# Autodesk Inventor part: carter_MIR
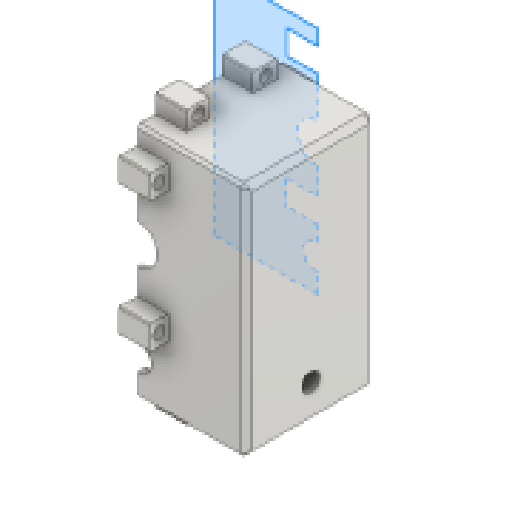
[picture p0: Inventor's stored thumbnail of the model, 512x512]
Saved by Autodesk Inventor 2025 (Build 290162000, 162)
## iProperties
Created: 2026-05
Part Number: carter_MIR
Material: Acciaio
Document SubType Name: Modeling
Designer: Ryzen5700u
Density: 7.85 g/cm^3
Appearance: Acciaio
Author: R5800u
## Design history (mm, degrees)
derived "carter.ipt"
  sketch "Schizzo1"
    geometry: L1 (0, -58)-(-160, -58) reference; L2 (-160, -58)-(-160, 332) reference; L3 (-160, 332)-(0, 332) reference; L4 (0, 332)-(0, -58) reference; C1 r 12 at (0, 0) reference; C2 r 31 at (0, 0) reference; C3 r 45 at (0, 162) reference; A1 r 19.5 centre (0, 162) between (18.547, 168.023) and (18.561, 156.023) reference; 1 further point
  sketch "Schizzo2"
    geometry: L1 (0, 390)-(-35, 390) reference; L2 (-210, 0)-(-210, 390) reference; L3 (0, 390)-(-210, 390) reference; L4 (-210, 390)-(-210, 0) reference; L5 (-210, 0)-(0, 0) reference; L6 (0, 0)-(0, 390) reference; 1 further point
  sketch "Schizzo3"
    geometry: L1 (175, 390)-(35, 390) reference; L2 (175, 390)-(175, 0) reference; L3 (35, 390)-(175, 390) reference; L4 (175, 390)-(175, 370) reference; L5 (175, 370)-(35, 370) reference; L6 (35, 370)-(35, 390) reference; L7 (0, 0)-(35, 0) reference; L8 (35, 0)-(175, 0) reference; L9 (175, 0)-(175, 20) reference; L10 (175, 20)-(35, 20) reference; L11 (35, 20)-(35, 0) reference; 1 further point
  sketch "Schizzo4"
    geometry: L1 (0, 170)-(0, 45) reference; L2 (0, 170)-(180, 170) reference; L3 (180, -220)-(180, 170) reference; L4 (0, -220)-(180, -220) reference; L5 (0, -193)-(0, -220) reference; L6 (0, -45)-(0, -131) reference; L7 (0, 45)-(0, -45) reference; C1 r 32.5 at (0, 0) reference; A1 r 31 centre (0, -162) between (0, -193) and (0, -131) reference; A2 r 45 centre (0, 0) between (0, -45) and (0, 45) reference; 1 further point
  sketch "Schizzo5"
    geometry: L1 (0, 332)-(0, 194.5) reference; L2 (0, 332)-(180, 332) reference; L3 (180, -58)-(180, 332) reference; L4 (0, -58)-(180, -58) reference; L5 (0, -31)-(0, -58) reference; L6 (0, 31)-(0, 129.5) reference; L7 (0, 31)-(0, -31) reference; C1 r 21 at (1.789, 0) reference; A1 r 31 centre (0, 0) between (0, -31) and (0, 31) reference; A2 r 32.5 centre (0, 162) between (0, 129.5) and (0, 194.5) reference; 1 further point
  sketch "Schizzo6"
    geometry: L1 (35, 120)-(30, 125) reference; L2 (35, 120)-(35, -12.5) reference; L3 (35, -12.5)-(28, -12.5) reference; L4 (28, 0)-(28, -12.5) reference; L5 (28, 0)-(0, 0) reference; L6 (0, 0)-(0, 105) reference; L7 (-140, 105)-(0, 105) reference; L8 (-140, 0)-(-140, 105) reference; L9 (-168, 0)-(-140, 0) reference; L10 (-168, 0)-(-168, -12.5) reference; L11 (-175, -12.5)-(-168, -12.5) reference; L12 (-175, 120)-(-175, -12.5) reference; L13 (-170, 125)-(-175, 120) reference; L14 (-170, 125)-(30, 125) reference; L15 (-175, -260)-(-170, -265) reference; L16 (-175, -227.924)-(-175, -260) reference; L17 (-175, -227.924)-(-162, -227.924) reference; L18 (-162, -227.924)-(-162, -238) reference; L19 (-162, -238)-(-140, -238) reference; L20 (-140, -245)-(-140, -238) reference; L21 (0, -245)-(-140, -245) reference; L22 (0, -245)-(0, -238) reference; L23 (22, -238)-(0, -238) reference; L24 (22, -227.924)-(22, -238) reference; L25 (35, -227.924)-(22, -227.924) reference; L26 (35, -260)-(35, -227.924) reference; L27 (30, -265)-(35, -260) reference; L28 (-170, -265)-(30, -265) reference; L29 (-175, -77.5)-(-175, -186.076) reference; L30 (-175, -77.5)-(-168, -77.5) reference; L31 (-168, -77.5)-(-168, -90) reference; L32 (-168, -90)-(-140, -90) reference; L33 (-140, -176)-(-140, -90) reference; L34 (-162, -176)-(-140, -176) reference; L35 (-162, -176)-(-162, -186.076) reference; L36 (-175, -186.076)-(-162, -186.076) reference; L37 (35, -186.076)-(35, -77.5) reference; L38 (35, -186.076)-(22, -186.076) reference; L39 (22, -176)-(22, -186.076) reference; L40 (22, -176)-(0, -176) reference; L41 (0, -176)-(0, -90) reference; L42 (28, -90)-(0, -90) reference; L43 (28, -77.5)-(28, -90) reference; L44 (35, -77.5)-(28, -77.5) reference; L45 (-125, 125)-(-125, -265) reference; L46 (30, 125)-(-170, 125) reference; L47 (-70, 125)-(-70, -265) reference; L48 (-15, 125)-(-15, -265) reference; L49 (-175, 75)-(35, 75) reference; L50 (35, -260)-(35, 120) reference; L51 (-145, 95)-(-205, 95) reference; L52 (-205, 95)-(-205, 55) reference; L53 (-205, 55)-(-145, 55) reference; L54 (-145, 55)-(-145, 95) reference; L55 (-145, 95)-(-205, 55) reference; L56 (-205, 95)-(-145, 55) reference; L57 (-145, -235)-(-105, -235) reference; L58 (-105, -235)-(-105, -295) reference; L59 (-105, -295)-(-145, -295) reference; L60 (-145, -295)-(-145, -235) reference; L61 (-145, -235)-(-105, -295) reference; L62 (-105, -235)-(-145, -295) reference; L63 (-35, -235)-(5, -235) reference; L64 (5, -235)-(5, -295) reference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
  sketch "Schizzo7"
    geometry: L1 (35, 120)-(30, 125) reference; L2 (35, 120)-(35, 95) reference; L3 (35, 95)-(65, 95) reference; L4 (65, 95)-(65, 55) reference; L5 (65, 55)-(35, 55) reference; L6 (35, 55)-(35, -12.5) reference; L7 (35, -12.5)-(28, -12.5) reference; L8 (28, 0)-(28, -12.5) reference; L9 (28, 0)-(0, 0) reference; L10 (0, 0)-(0, 105) reference; L11 (-140, 105)-(0, 105) reference; L12 (-140, 0)-(-140, 105) reference; L13 (-168, 0)-(-140, 0) reference; L14 (-168, 0)-(-168, -12.5) reference; L15 (-175, -12.5)-(-168, -12.5) reference; L16 (-175, 55)-(-175, -12.5) reference; L17 (-175, 55)-(-205, 55) reference; L18 (-205, 55)-(-205, 95) reference; L19 (-205, 95)-(-175, 95) reference; L20 (-175, 120)-(-175, 95) reference; L21 (-170, 125)-(-175, 120) reference; L22 (-170, 125)-(-145, 125) reference; L23 (-145, 125)-(-145, 155) reference; L24 (-145, 155)-(-105, 155) reference; L25 (-105, 155)-(-105, 125) reference; L26 (-105, 125)-(-35, 125) reference; L27 (-35, 125)-(-35, 155) reference; L28 (-35, 155)-(5, 155) reference; L29 (5, 155)-(5, 125) reference; L30 (5, 125)-(30, 125) reference; L31 (35, -186.076)-(35, -160) reference; L32 (35, -186.076)-(22, -186.076) reference; L33 (22, -176)-(22, -186.076) reference; L34 (22, -176)-(0, -176) reference; L35 (0, -176)-(0, -90) reference; L36 (28, -90)-(0, -90) reference; L37 (28, -77.5)-(28, -90) reference; L38 (35, -77.5)-(28, -77.5) reference; L39 (35, -120)-(35, -77.5) reference; L40 (35, -120)-(65, -120) reference; L41 (65, -120)-(65, -160) reference; L42 (65, -160)-(35, -160) reference; L43 (5, -265)-(-35, -265) reference; L44 (-175, -260)-(-170, -265) reference; L45 (-175, -227.924)-(-175, -260) reference; L46 (-175, -227.924)-(-162, -227.924) reference; L47 (-162, -227.924)-(-162, -238) reference; L48 (-162, -238)-(-140, -238) reference; L49 (-140, -245)-(-140, -238) reference; L50 (0, -245)-(-140, -245) reference; L51 (0, -245)-(0, -238) reference; L52 (22, -238)-(0, -238) reference; L53 (22, -227.924)-(22, -238) reference; L54 (35, -227.924)-(22, -227.924) reference; L55 (35, -260)-(35, -227.924) reference; L56 (30, -265)-(35, -260) reference; L57 (5, -265)-(30, -265) reference; L58 (5, -265)-(5, -295) reference; L59 (5, -295)-(-35, -295) reference; L60 (-35, -295)-(-35, -265) reference; L61 (-105, -265)-(-35, -265) reference; L62 (-105, -265)-(-105, -295) reference; L63 (-105, -295)-(-145, -295) reference; L64 (-145, -295)-(-145, -265) reference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; 9 further points
  sketch "Schizzo8"
    geometry: L1 (-160, 30)-(-160, 170) reference; L2 (-160, 100)-(-144, 100) reference; 1 further point
  node "Piano di lavoro1"
  node "Piano di lavoro2"
  node "Piano di lavoro3"
  node "Piano di lavoro4"
sketch "Schizzo9"
  geometry: L1 (80, 65)-(0, 65) reference; L2 (80, 65)-(80, 25) reference; L3 (0, 25)-(80, 25) reference; L4 (0, 0)-(0, 25) reference; L5 (0, 0)-(145, 0) reference; L6 (180, 50)-(180, 150) reference; L7 (145, 200)-(0, 200) reference; L8 (0, 175)-(0, 200) reference; L9 (80, 175)-(0, 175) reference; L10 (80, 175)-(80, 135) reference; L11 (0, 135)-(80, 135) reference; L12 (0, 65)-(0, 135) reference; L13 (180, 50)-(145, 50) reference; L14 (145, 150)-(180, 150) reference; L15 (145, 0)-(145, 50) reference; L16 (145, 150)-(145, 200) reference; C1 r 14.917 at (144, 100) reference; 1 further point
extrude "Estrusione1" join sketch "Schizzo9" stored distance "d1" = 10; taper "d2" = 0 deg
sketch "Schizzo10"
  geometry: L1 (5, 385)-(0, 380) reference; L2 (0, 0)-(0, 380) reference; L3 (0, 0)-(5, -5) reference; L4 (155, -5)-(55, -5) reference; L5 (205, -5)-(210, 0) reference; L6 (210, 380)-(210, 0) reference; L7 (210, 380)-(205, 385) reference; L8 (55, 385)-(155, 385) reference; L9 (5, -50)-(5, -5) reference; L10 (50, -55)-(10, -55) reference; L11 (55, -5)-(55, -50) reference; L12 (155, -50)-(155, -5) reference; L13 (200, -55)-(160, -55) reference; L14 (205, -5)-(205, -50) reference; L15 (205, 430)-(205, 385) reference; L16 (160, 435)-(200, 435) reference; L17 (155, 385)-(155, 430) reference; L18 (55, 430)-(55, 385) reference; L19 (10, 435)-(50, 435) reference; L20 (5, 385)-(5, 430) reference; L21 (205, 430)-(200, 435) reference; L22 (160, 435)-(155, 430) reference; L23 (55, 430)-(50, 435) reference; L24 (10, 435)-(5, 430) reference; L25 (5, -50)-(10, -55) reference; L26 (50, -55)-(55, -50) reference; L27 (155, -50)-(160, -55) reference; L28 (200, -55)-(205, -50) reference; L29 (5, -5)-(205, -5); L30 (5, 385)-(205, 385); C1 r 270.277 at (103.909, 191.96); 6 further points
  constraints: 4 end point, 1 centre point, 1 horizontal, 1 parallel, 1 point on line
extrude "Estrusione2" cut sketch "Schizzo10" distance "d3" = 130; taper "d4" = 0 deg
sketch "Schizzo11"
  geometry: C1 r 5.053 at (225, 335) reference; C2 r 5.053 at (225, 120) reference; C3 r 5.053 at (160, 400) reference; C4 r 5.053 at (50, 400) reference; C5 r 5.053 at (-15, 335) reference; C6 r 5.053 at (-15, 120) reference; C7 r 5.053 at (50, -20) reference; C8 r 5.053 at (160, -20) reference; 1 further point
hole "Foro1" sketch "Schizzo11" at (-15, 335), (-15, 120), (50, -20), (160, -20), (225, 120), (225, 335), (160, 400), (50, 400) diameter "d5" = 10.106; stored, may be unused: countersink angle "d9" = 90 deg, drill point angle "d11" = 118 deg; dims "d6" = 24, "d7" = 20, "d8" = 15, "d10" = 8
chamfer "Smusso1" distance "d12" = 10; stored, may be unused: second distance "d13" = 2, angle "d14" = 45 deg
sketch "Schizzo12"
  geometry: L1 (-60, -10)-(-130, -10) reference; L2 (-95, -10)-(-95, 50); 1 further point
  constraints: 2 end point, 1 midpoint, 1 vertical
  dimensions: "d15" = 60 distance of L2.start L2.end
hole "Foro2" sketch "Schizzo12" at (-95, 50) diameter "d16" = 29.83494; stored, may be unused: countersink angle "d20" = 90 deg, drill point angle "d22" = 118 deg; dims "d17" = 64, "d18" = 20, "d19" = 15, "d21" = 8
feature "Solido1::carter.ipt" dims "d0" = 10
tag "Lavorazione contrassegno1"
node "Linea chiusa proiettata1"
node "Linea chiusa proiettata2"
node "Solido1"
